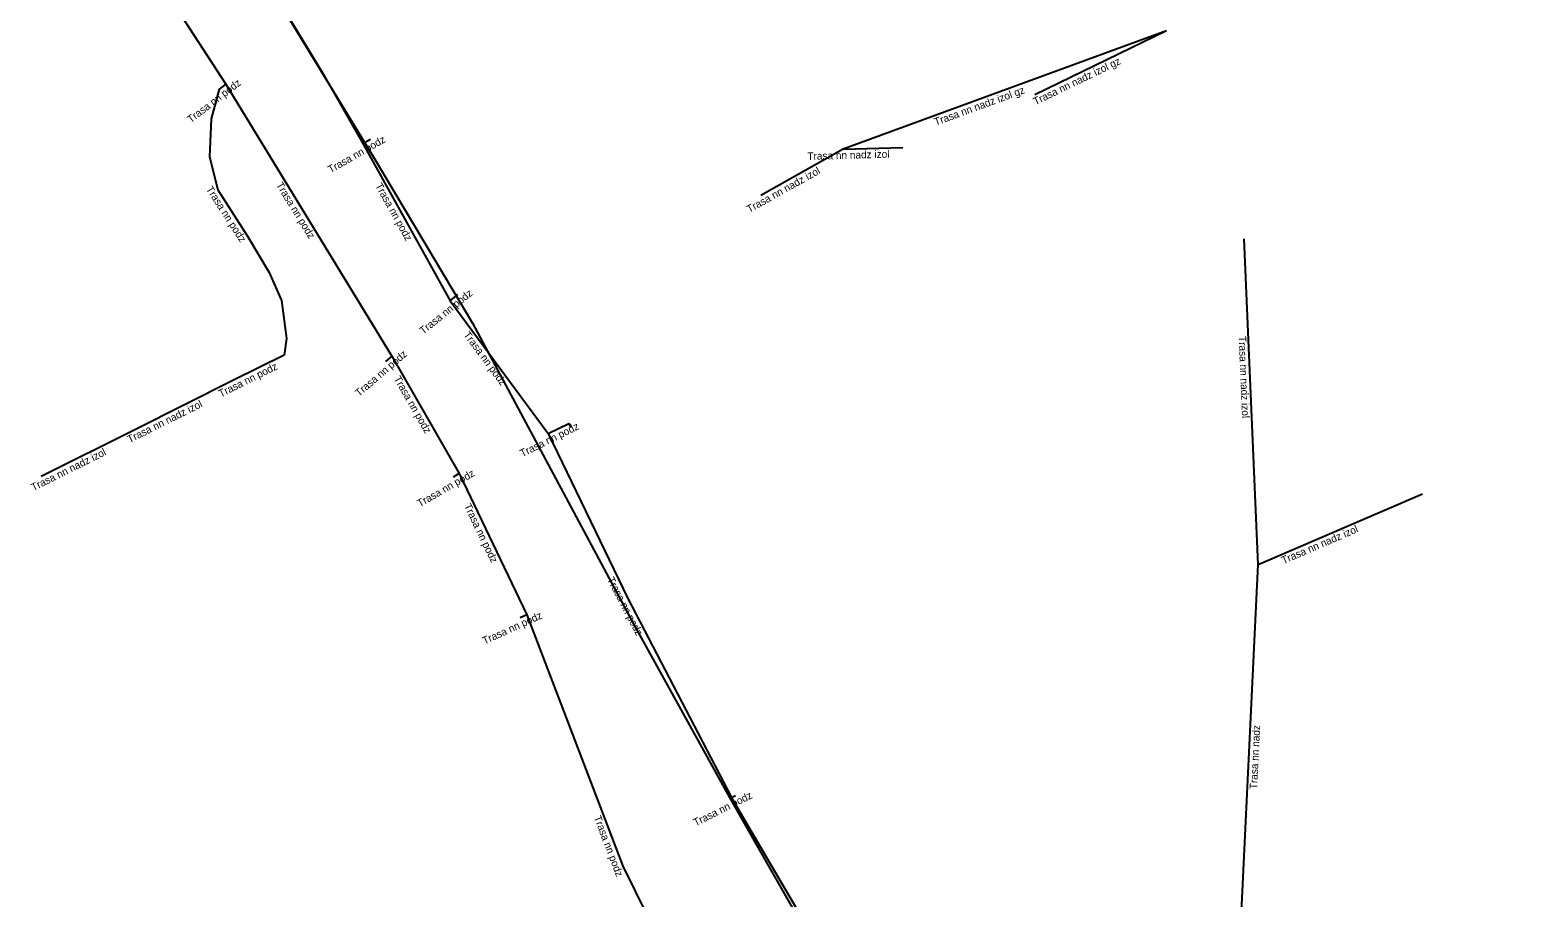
# Model space of a CAD drawing. Extents: x -748073 to -746986, y -1069233 to -1068700.
# Drawn here: x -747576.3 to -747476, y -1068883.9 to -1068826.2 of the extents above; entities that cross this region are included whole.
import ezdxf

# ---------------------------------------------------------------- set-up
doc = ezdxf.new("R2010")
doc.units = 0
for name, color, linetype in [('Popiskový text - Ostatní atributy Trasy', 7, 'Continuous'), ('Spojnice NN', 7, 'Continuous'), ('Spojnice VN', 7, 'Continuous')]:
    doc.layers.add(name, color=color, linetype=linetype)

msp = doc.modelspace()

# ---------------------------------------------------------------- linework, layer by layer
at = {"layer": 'Spojnice NN'}
for points in [[(-747572.99, -1068814.86), (-747563.29, -1068829.82)], [(-747564.72, -1068816.09), (-747556.85, -1068829.06), (-747554.16, -1068833.77)], [(-747500.73, -1068826.27), (-747522.22, -1068834.14)], [(-747500.73, -1068826.27), (-747509.48, -1068830.52)], [(-747563.29, -1068829.82), (-747563.72, -1068830.15)], [(-747563.29, -1068829.82), (-747552.24, -1068847.9)], [(-747563.72, -1068830.15), (-747564.25, -1068832.12), (-747564.36, -1068834.65), (-747563.81, -1068836.85), (-747561.83, -1068839.93), (-747560.4, -1068842.34), (-747559.58, -1068844.21), (-747559.25, -1068846.74), (-747559.41, -1068847.84)], [(-747554.16, -1068833.77), (-747553.65, -1068833.48)], [(-747554.16, -1068833.77), (-747548.37, -1068844.22)], [(-747522.22, -1068834.14), (-747518.25, -1068834.03)], [(-747522.22, -1068834.14), (-747527.7, -1068837.21)], [(-747494.63, -1068861.77), (-747495.56, -1068840.1)], [(-747548.37, -1068844.22), (-747547.85, -1068843.8)], [(-747548.37, -1068844.22), (-747541.84, -1068853.06)], [(-747559.41, -1068847.84), (-747562.76, -1068849.51)], [(-747552.24, -1068847.9), (-747552.67, -1068848.27)], [(-747552.24, -1068847.9), (-747547.77, -1068855.72)], [(-747562.76, -1068849.51), (-747569.33, -1068852.8)], [(-747569.33, -1068852.8), (-747575.57, -1068855.92)], [(-747541.84, -1068853.06), (-747540.47, -1068852.38), (-747540.34, -1068852.6)], [(-747541.84, -1068853.06), (-747536.55, -1068864.03), (-747529.66, -1068877.28)], [(-747547.77, -1068855.72), (-747548.17, -1068855.95)], [(-747547.77, -1068855.72), (-747543.26, -1068865.11)], [(-747494.63, -1068861.77), (-747483.71, -1068857.07)], [(-747495.77, -1068885.35), (-747494.63, -1068861.77)], [(-747543.26, -1068865.11), (-747543.7, -1068865.31)], [(-747543.26, -1068865.11), (-747536.89, -1068881.84), (-747534.45, -1068886.78), (-747533.6, -1068889.94), (-747529.02, -1068896.45)], [(-747529.66, -1068877.28), (-747529.38, -1068877.14)], [(-747500.32, -1068923.85), (-747502.81, -1068918.56), (-747510.97, -1068903.91), (-747522.08, -1068890.2), (-747529.66, -1068877.28)]]:
    msp.add_lwpolyline(points, dxfattribs=at)
at = {"layer": 'Spojnice VN'}
msp.add_lwpolyline([(-747568.78, -1068809.51), (-747553.42, -1068834.74), (-747546.88, -1068845.72), (-747536.13, -1068865.8), (-747529.79, -1068877.28), (-747523.97, -1068887.47), (-747516.4, -1068898.07), (-747510.89, -1068906.78), (-747504.76, -1068915.72), (-747500.03, -1068925.46), (-747496.8, -1068934.07), (-747493.21, -1068943.29), (-747484.24, -1068967.84), (-747480.06, -1068978.57), (-747476.03, -1068989.72)], dxfattribs=at)

# ---------------------------------------------------------------- texts
at = {"layer": 'Popiskový text - Ostatní atributy Trasy'}
for s, rotation, p in [('Trasa nn nadz izol gz', 25.8986, (-747509.44, -1068831.22)), ('Trasa nn podz', 37.5041, (-747565.61, -1068832.42)), ('Trasa nn nadz izol gz', 20.1232, (-747516.07, -1068832.58)), ('Trasa nn podz', 29.6237, (-747556.32, -1068835.75)), ('Trasa nn nadz izol', 1.6898, (-747524.6, -1068834.86)), ('Trasa nn nadz izol', 29.2192, (-747528.47, -1068838.39)), ('Trasa nn podz', 302.7376, (-747564.62, -1068836.79)), ('Trasa nn podz', 301.4321, (-747559.96, -1068836.51)), ('Trasa nn podz', 298.9894, (-747553.36, -1068836.56)), ('Trasa nn podz', 38.9275, (-747550.15, -1068846.49)), ('Trasa nn podz', 306.4528, (-747547.5, -1068846.49)), ('Trasa nn nadz izol', 272.4362, (-747495.93, -1068846.58)), ('Trasa nn podz', 40.7108, (-747554.42, -1068850.63)), ('Trasa nn podz', 26.5668, (-747563.61, -1068850.66)), ('Trasa nn podz', 299.7528, (-747552.13, -1068849.4)), ('Trasa nn nadz izol', 26.5651, (-747569.68, -1068853.7)), ('Trasa nn podz', 26.3975, (-747543.57, -1068854.64)), ('Trasa nn nadz izol', 26.5651, (-747576.08, -1068856.9)), ('Trasa nn podz', 29.8989, (-747550.38, -1068857.97)), ('Trasa nn podz', 295.6549, (-747547.46, -1068857.86)), ('Trasa nn nadz izol', 23.3112, (-747492.95, -1068861.75)), ('Trasa nn podz', 297.4744, (-747537.94, -1068862.76)), ('Trasa nn podz', 24.444, (-747546.08, -1068867.1)), ('Trasa nn nadz', 87.2508, (-747494.7, -1068876.73)), ('Trasa nn podz', 26.5651, (-747532.04, -1068879.2)), ('Trasa nn podz', 290.8445, (-747538.82, -1068878.59))]:
    msp.add_text(s, height=0.5, rotation=rotation, dxfattribs=at).set_placement(p)

doc.saveas('drawing.dxf')
